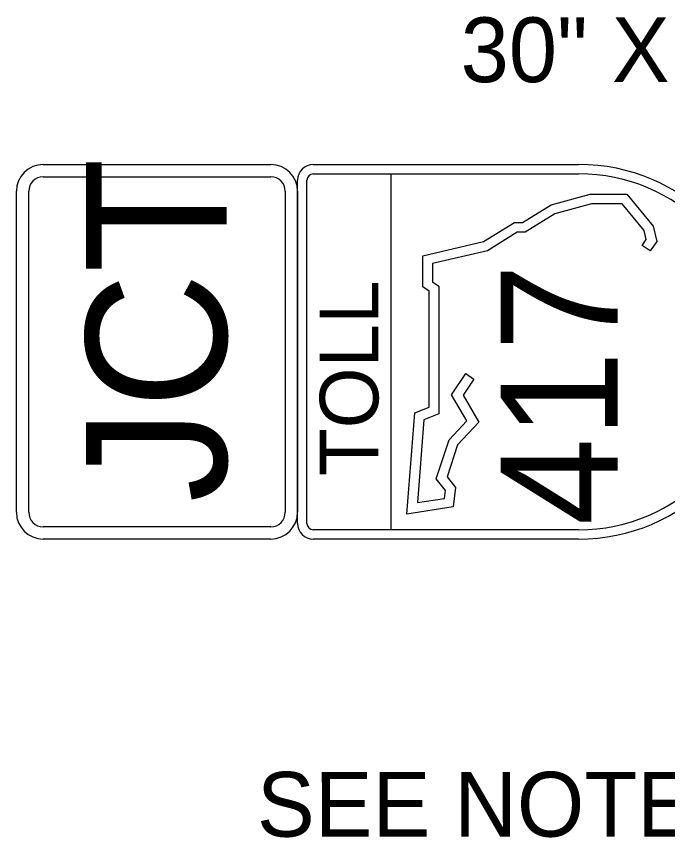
# Model space of a CAD drawing. Extents: x -830008.4 to -829992.7, y 1290284.1 to 1290294.4.
# Drawn here: x -829994.824 to -829994.121, y 1290292.403 to 1290293.291 of the extents above; entities that cross this region are included whole.
import ezdxf

# ---------------------------------------------------------------- set-up
doc = ezdxf.new("R2010")
doc.units = 0
doc.layers.add('1', color=7, linetype='Continuous')
doc.layers.add('SheetBorder_dp', color=7, linetype='Continuous')

msp = doc.modelspace()

# ---------------------------------------------------------------- linework, layer by layer
at = {"layer": 'SheetBorder_dp'}
for p, q in [((-829994.24647, 1290293.08747), (-829994.20409, 1290293.09905)), ((-829994.20409, 1290293.09905), (-829994.16448, 1290293.09905)), ((-829994.16448, 1290293.09905), (-829994.13617, 1290293.06451)), ((-829994.27746, 1290293.06865), (-829994.24647, 1290293.08747)), ((-829994.20267, 1290293.0885), (-829994.24226, 1290293.07768)), ((-829994.16947, 1290293.0885), (-829994.20267, 1290293.0885)), ((-829994.14586, 1290293.0597), (-829994.16947, 1290293.0885)), ((-829994.24226, 1290293.07768), (-829994.2745, 1290293.0581)), ((-829994.31931, 1290293.04785), (-829994.28589, 1290293.06865)), ((-829994.28589, 1290293.06865), (-829994.27746, 1290293.06865)), ((-829994.13617, 1290293.06451), (-829994.13224, 1290293.0481)), ((-829994.28288, 1290293.0581), (-829994.31522, 1290293.03797)), ((-829994.2745, 1290293.0581), (-829994.28288, 1290293.0581)), ((-829994.14359, 1290293.05024), (-829994.14586, 1290293.0597)), ((-829994.38506, 1290293.03257), (-829994.31931, 1290293.04785)), ((-829994.14812, 1290293.04372), (-829994.14359, 1290293.05024)), ((-829994.13224, 1290293.0481), (-829994.13945, 1290293.0377)), ((-829994.31522, 1290293.03797), (-829994.37451, 1290293.0242)), ((-829994.13945, 1290293.0377), (-829994.14812, 1290293.04372)), ((-829994.38506, 1290292.99882), (-829994.38506, 1290293.03257)), ((-829994.37451, 1290293.0242), (-829994.37451, 1290293.00442)), ((-829994.37451, 1290293.00442), (-829994.36753, 1290292.9997)), ((-829994.37807, 1290292.9941), (-829994.38506, 1290292.99882)), ((-829994.37807, 1290292.86866), (-829994.37807, 1290292.9941)), ((-829994.36753, 1290292.9997), (-829994.36753, 1290292.86145)), ((-829994.354, 1290292.88223), (-829994.33855, 1290292.90508)), ((-829994.33855, 1290292.90508), (-829994.32981, 1290292.89917)), ((-829994.32981, 1290292.89917), (-829994.34153, 1290292.88184)), ((-829994.3375, 1290292.85416), (-829994.354, 1290292.88223)), ((-829994.34153, 1290292.88184), (-829994.32443, 1290292.85274)), ((-829994.3938, 1290292.86254), (-829994.37807, 1290292.86866)), ((-829994.40224, 1290292.75318), (-829994.3938, 1290292.86254)), ((-829994.36753, 1290292.86145), (-829994.38379, 1290292.85512)), ((-829994.38379, 1290292.85512), (-829994.3907, 1290292.76565)), ((-829994.35669, 1290292.83345), (-829994.3375, 1290292.85416)), ((-829994.32443, 1290292.85274), (-829994.34737, 1290292.82799)), ((-829994.37041, 1290292.79126), (-829994.35669, 1290292.83345)), ((-829994.34737, 1290292.82799), (-829994.35864, 1290292.79336)), ((-829994.36063, 1290292.77883), (-829994.37041, 1290292.79126)), ((-829994.35864, 1290292.79336), (-829994.34963, 1290292.7819)), ((-829994.34963, 1290292.7819), (-829994.35221, 1290292.76097)), ((-829994.36171, 1290292.77016), (-829994.36063, 1290292.77883)), ((-829994.3907, 1290292.76565), (-829994.36171, 1290292.77016)), ((-829994.35221, 1290292.76097), (-829994.40224, 1290292.75318))]:
    msp.add_line(p, q, dxfattribs=at)
for points in [[(-829994.79518, 1290293.13118), (-829994.54929, 1290293.13118)], [(-829994.50349, 1290293.13118), (-829994.21661, 1290293.13118)], [(-829994.7952, 1290293.11792), (-829994.54929, 1290293.11792)], [(-829994.50349, 1290293.12106), (-829994.21661, 1290293.12106)], [(-829994.41911, 1290292.73631), (-829994.41911, 1290293.12106)], [(-829994.52036, 1290292.74306), (-829994.52036, 1290293.11431)], [(-829994.51024, 1290292.74306), (-829994.51024, 1290293.11431)], [(-829994.82411, 1290292.75511), (-829994.82411, 1290293.10225)], [(-829994.81085, 1290292.75511), (-829994.81085, 1290293.10225)], [(-829994.53362, 1290293.10225), (-829994.53362, 1290292.75511)], [(-829994.52036, 1290293.10225), (-829994.52036, 1290292.75511)], [(-829994.54929, 1290292.73944), (-829994.7952, 1290292.73944)], [(-829994.21661, 1290292.73631), (-829994.50349, 1290292.73631)], [(-829994.54929, 1290292.72618), (-829994.79518, 1290292.72618)], [(-829994.21661, 1290292.72618), (-829994.50349, 1290292.72618)]]:
    msp.add_lwpolyline(points, dxfattribs=at)
for centre, radius, start, end in [((-829994.79518, 1290293.10225), 0.02893, 90, 180), ((-829994.54929, 1290293.10225), 0.02893, 0, 90), ((-829994.50349, 1290293.11431), 0.01687, 90, 180), ((-829994.21661, 1290292.92868), 0.2025, 270, 90), ((-829994.79518, 1290293.10225), 0.01567, 90.0544, 180), ((-829994.54929, 1290293.10225), 0.01567, 0, 90), ((-829994.50349, 1290293.11431), 0.00675, 90, 180), ((-829994.21661, 1290292.92868), 0.19238, 270, 90), ((-829994.79518, 1290292.75511), 0.02893, 180, 270), ((-829994.79518, 1290292.75511), 0.01567, 180, 269.9456), ((-829994.54929, 1290292.75511), 0.02893, 270, 0), ((-829994.54929, 1290292.75511), 0.01567, 270, 0), ((-829994.50349, 1290292.74306), 0.01687, 180, 270), ((-829994.50349, 1290292.74306), 0.00675, 180, 270)]:
    msp.add_arc(centre, radius, start, end, dxfattribs=at)

# ---------------------------------------------------------------- texts
at = {"layer": '1'}
for s, p in [('30" X 26"  ', (-829994.34412, 1290293.22021)), ('SEE NOTE 1 AND 2', (-829994.56423, 1290292.40444))]:
    msp.add_text(s, height=0.07, rotation=0.00437, dxfattribs=at).set_placement(p)
at = {"layer": 'SheetBorder_dp'}
for s, height, p in [('JCT', 0.151875, (-829994.59708, 1290292.76576)), ('417', 0.126563, (-829994.17439, 1290292.7413)), ('TOLL', 0.063281, (-829994.43303, 1290292.79425))]:
    msp.add_text(s, height=height, rotation=90, dxfattribs=at).set_placement(p)

doc.saveas('drawing.dxf')
